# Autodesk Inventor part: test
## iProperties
Created: 2002-02
Part Number: test
Document SubType Name: Modeling
Designer: ***
Control State: 0
Master: False
Checked Out: False
Shininess: 65.0
Angle Display Precision: 2
Document Length Units: 11269
Document Angle Units: 11279
Document Time Units: 11290
Document Mass Units: 11283
Document Length Units Precision: 3
Document Angle Units Precision: 2
Density: 0.0
Volumn: 0.0
Area: 0.0
PropertySet Name: Model Information
Author: ***
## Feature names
1. Extrusion1
2. Hole1
3. Circular Pattern1
